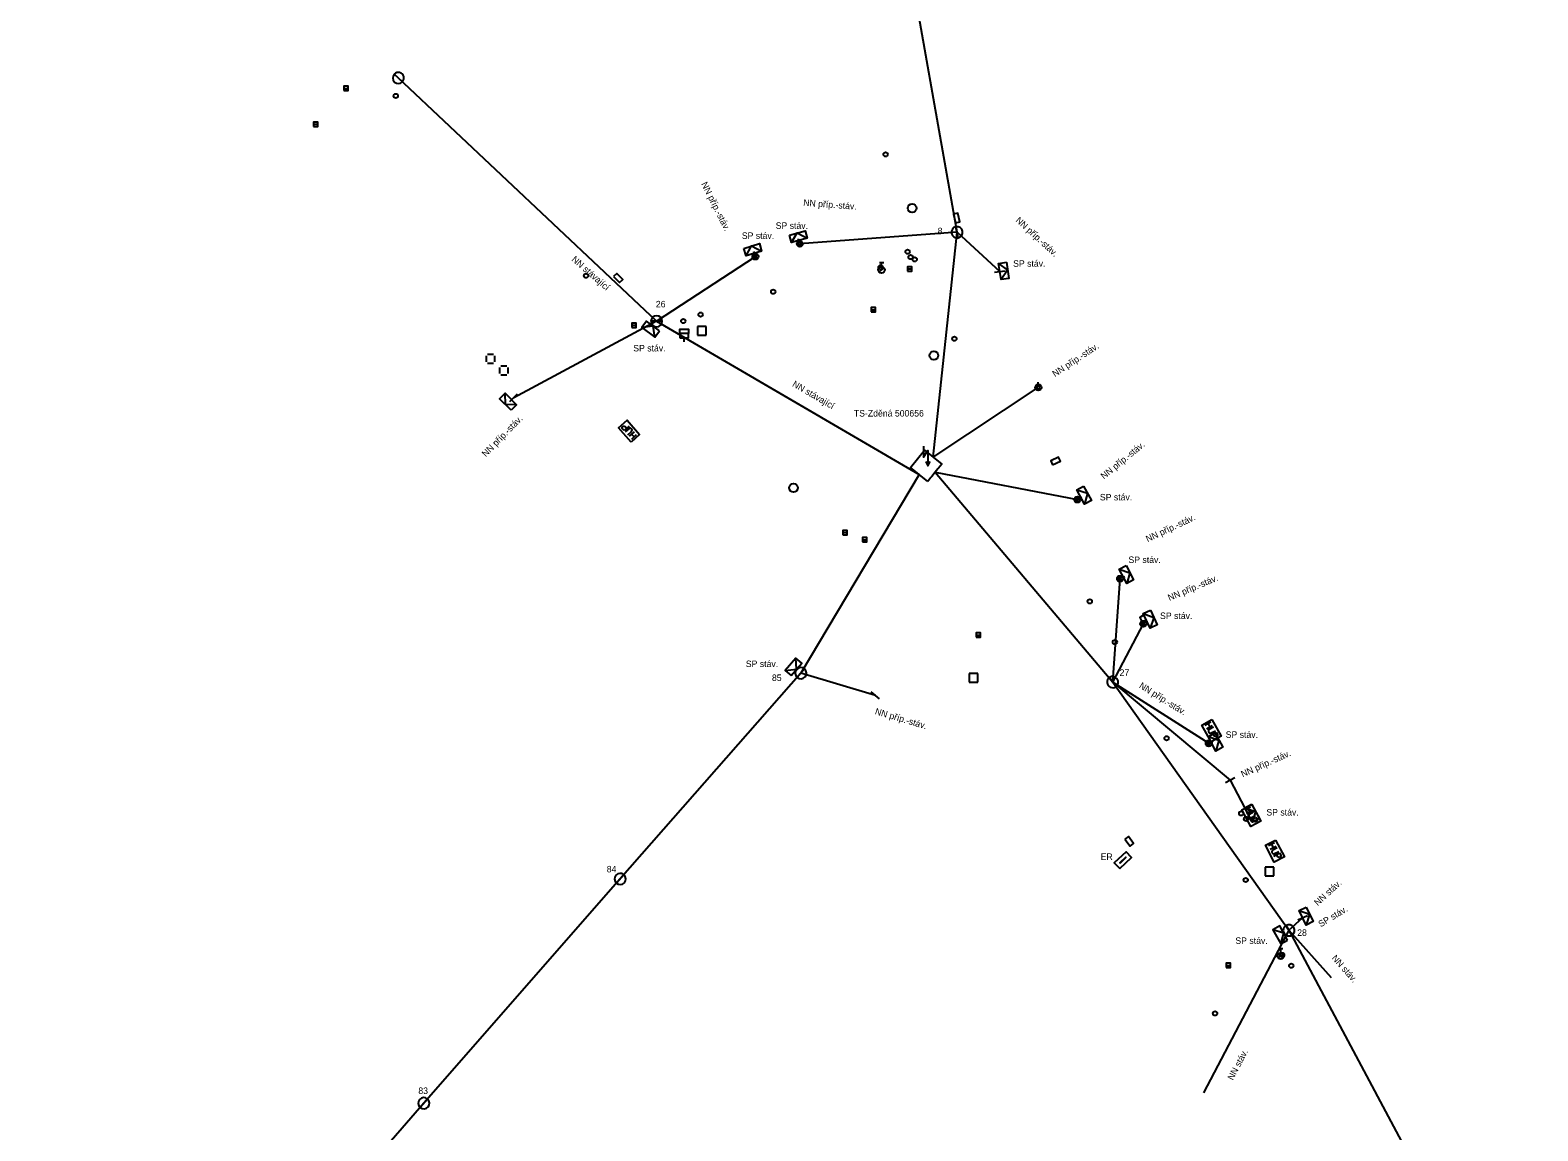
# Model space of a CAD drawing. Extents: x -577028 to -568584, y -1207664 to -1202947.
# Drawn here: x -573521.3 to -573347.2, y -1206639.6 to -1206512.4 of the extents above; entities that cross this region are included whole.
import ezdxf

# ---------------------------------------------------------------- set-up
doc = ezdxf.new("R2010")
doc.units = 0
for name, color, linetype in [('CIZÍ_NADZEM', 7, 'Continuous'), ('ELE_EON', 7, 'Continuous'), ('ELE_EON_POPIS', 7, 'Continuous')]:
    doc.layers.add(name, color=color, linetype=linetype)

msp = doc.modelspace()

# ---------------------------------------------------------------- linework, layer by layer
at = {"layer": 'CIZÍ_NADZEM'}
for p, q in [((-573485.11, -1206519.14), (-573484.61, -1206519.14)), ((-573488.61, -1206523.27), (-573488.11, -1206523.27)), ((-573423.29, -1206540.34), (-573422.7, -1206539.88)), ((-573423.25, -1206539.24), (-573422.75, -1206539.24)), ((-573423, -1206539.74), (-573423, -1206539.24)), ((-573420.02, -1206539.99), (-573419.52, -1206539.99)), ((-573424.19, -1206544.71), (-573423.69, -1206544.71)), ((-573451.86, -1206546.5), (-573451.36, -1206546.5)), ((-573443.27, -1206546.64), (-573444.27, -1206546.64)), ((-573444.27, -1206546.64), (-573444.27, -1206547.64)), ((-573443.27, -1206547.64), (-573443.27, -1206546.64)), ((-573445.81, -1206548.43), (-573445.81, -1206547.93)), ((-573444.27, -1206547.64), (-573443.27, -1206547.64)), ((-573468.65, -1206550.01), (-573468.65, -1206550.71)), ((-573467.8, -1206549.86), (-573468.5, -1206549.86)), ((-573467.65, -1206550.71), (-573467.65, -1206550.01)), ((-573468.5, -1206550.86), (-573467.8, -1206550.86)), ((-573467.13, -1206551.38), (-573467.13, -1206552.08)), ((-573466.28, -1206551.23), (-573466.98, -1206551.23)), ((-573466.98, -1206552.23), (-573466.28, -1206552.23)), ((-573466.13, -1206552.08), (-573466.13, -1206551.38)), ((-573427.48, -1206570.45), (-573426.98, -1206570.45)), ((-573425.2, -1206571.28), (-573424.7, -1206571.28)), ((-573412.09, -1206582.28), (-573411.59, -1206582.28)), ((-573411.9, -1206586.71), (-573412.9, -1206586.71)), ((-573412.9, -1206586.71), (-573412.9, -1206587.71)), ((-573411.9, -1206587.71), (-573411.9, -1206586.71)), ((-573412.9, -1206587.71), (-573411.9, -1206587.71)), ((-573377.71, -1206609.1), (-573378.71, -1206609.1)), ((-573378.71, -1206609.1), (-573378.71, -1206610.1)), ((-573377.71, -1206610.1), (-573377.71, -1206609.1)), ((-573378.71, -1206610.1), (-573377.71, -1206610.1)), ((-573377.16, -1206618.49), (-573376.66, -1206618.49)), ((-573376.91, -1206618.99), (-573376.91, -1206618.49)), ((-573377.2, -1206619.59), (-573376.61, -1206619.13)), ((-573383.22, -1206620.45), (-573382.72, -1206620.45))]:
    msp.add_line(p, q, dxfattribs=at)
for points in [[(-573485.11, -1206519.39), (-573484.61, -1206519.39), (-573484.61, -1206518.89), (-573485.11, -1206518.89)], [(-573488.61, -1206523.52), (-573488.11, -1206523.52), (-573488.11, -1206523.02), (-573488.61, -1206523.02)], [(-573414.69, -1206533.67), (-573414.45, -1206534.65), (-573413.97, -1206534.53), (-573414.21, -1206533.55)], [(-573420.02, -1206540.24), (-573419.52, -1206540.24), (-573419.52, -1206539.74), (-573420.02, -1206539.74)], [(-573453.95, -1206540.85), (-573453.25, -1206541.56), (-573452.89, -1206541.21), (-573453.59, -1206540.5)], [(-573424.19, -1206544.96), (-573423.69, -1206544.96), (-573423.69, -1206544.46), (-573424.19, -1206544.46)], [(-573451.86, -1206546.75), (-573451.36, -1206546.75), (-573451.36, -1206546.25), (-573451.86, -1206546.25)], [(-573446.31, -1206547.93), (-573445.31, -1206547.93), (-573445.31, -1206547.43), (-573446.31, -1206547.43)], [(-573403.27, -1206562.61), (-573402.35, -1206562.21), (-573402.55, -1206561.75), (-573403.47, -1206562.15)], [(-573427.48, -1206570.7), (-573426.98, -1206570.7), (-573426.98, -1206570.2), (-573427.48, -1206570.2)], [(-573425.2, -1206571.53), (-573424.7, -1206571.53), (-573424.7, -1206571.03), (-573425.2, -1206571.03)], [(-573412.09, -1206582.53), (-573411.59, -1206582.53), (-573411.59, -1206582.03), (-573412.09, -1206582.03)], [(-573394.89, -1206605.87), (-573394.28, -1206606.66), (-573393.89, -1206606.35), (-573394.5, -1206605.56)], [(-573383.22, -1206620.7), (-573382.72, -1206620.7), (-573382.72, -1206620.2), (-573383.22, -1206620.2)]]:
    msp.add_lwpolyline(points, close=True, dxfattribs=at)
for points in [[(-573446.31, -1206547.43), (-573446.31, -1206546.93), (-573445.31, -1206546.93), (-573445.31, -1206547.43)], [(-573451.92, -1206559.99), (-573453.39, -1206558.35), (-573452.4, -1206557.47), (-573450.94, -1206559.11), (-573451.92, -1206559.99)], [(-573452.74, -1206558.66), (-573452.93, -1206558.45), (-573452.97, -1206558.35), (-573452.96, -1206558.31), (-573452.93, -1206558.23), (-573452.85, -1206558.16), (-573452.77, -1206558.14), (-573452.72, -1206558.14), (-573452.63, -1206558.18), (-573452.44, -1206558.39)], [(-573452.17, -1206558.15), (-573452.74, -1206558.66)], [(-573452.3, -1206559.15), (-573451.89, -1206558.78), (-573451.83, -1206558.69), (-573451.82, -1206558.59), (-573451.86, -1206558.49), (-573451.9, -1206558.45), (-573451.99, -1206558.4), (-573452.08, -1206558.4), (-573452.19, -1206558.45), (-573452.6, -1206558.82)], [(-573451.58, -1206558.8), (-573452.16, -1206559.31)], [(-573451.59, -1206559.4), (-573451.89, -1206559.07)], [(-573451.86, -1206559.64), (-573451.29, -1206559.13)], [(-573418.15, -1206560.48), (-573418.15, -1206561.73), (-573417.65, -1206560.98), (-573417.65, -1206562.73)], [(-573417.9, -1206562.23), (-573417.65, -1206562.73), (-573417.4, -1206562.23)], [(-573392.75, -1206580), (-573393.19, -1206580.24), (-573392.92, -1206580.79), (-573392.46, -1206580.54)], [(-573384.85, -1206592.04), (-573383.78, -1206593.96), (-573384.93, -1206594.6), (-573386.01, -1206592.68), (-573384.85, -1206592.04)], [(-573384.99, -1206592.36), (-573385.66, -1206592.74)], [(-573385.44, -1206593.12), (-573384.77, -1206592.75)], [(-573385.3, -1206592.54), (-573385.09, -1206592.93)], [(-573384.66, -1206592.94), (-573385.15, -1206593.21), (-573385.23, -1206593.29), (-573385.26, -1206593.38), (-573385.24, -1206593.48), (-573385.21, -1206593.54), (-573385.14, -1206593.6), (-573385.04, -1206593.62), (-573384.93, -1206593.59), (-573384.45, -1206593.33)], [(-573385.02, -1206593.89), (-573384.34, -1206593.52)], [(-573384.34, -1206593.52), (-573384.2, -1206593.77), (-573384.19, -1206593.86), (-573384.21, -1206593.91), (-573384.25, -1206593.97), (-573384.35, -1206594.03), (-573384.43, -1206594.03), (-573384.48, -1206594.02), (-573384.55, -1206593.96), (-573384.69, -1206593.71)], [(-573380.24, -1206601.84), (-573379.21, -1206603.78), (-573380.37, -1206604.4), (-573381.41, -1206602.46), (-573380.24, -1206601.84)], [(-573380.38, -1206602.16), (-573381.06, -1206602.52)], [(-573380.85, -1206602.91), (-573380.17, -1206602.55)], [(-573380.7, -1206602.33), (-573380.49, -1206602.72)], [(-573380.07, -1206602.75), (-573380.56, -1206603), (-573380.64, -1206603.08), (-573380.67, -1206603.18), (-573380.66, -1206603.28), (-573380.63, -1206603.33), (-573380.55, -1206603.4), (-573380.46, -1206603.42), (-573380.35, -1206603.39), (-573379.86, -1206603.14)], [(-573380.44, -1206603.69), (-573379.76, -1206603.33)], [(-573379.76, -1206603.33), (-573379.63, -1206603.58), (-573379.62, -1206603.68), (-573379.63, -1206603.73), (-573379.68, -1206603.79), (-573379.78, -1206603.84), (-573379.86, -1206603.85), (-573379.9, -1206603.83), (-573379.98, -1206603.77), (-573380.11, -1206603.52)], [(-573377.5, -1206605.97), (-573376.48, -1206607.92), (-573377.65, -1206608.53), (-573378.67, -1206606.57), (-573377.5, -1206605.97)], [(-573377.64, -1206606.29), (-573378.32, -1206606.64)], [(-573378.12, -1206607.03), (-573377.43, -1206606.68)], [(-573377.96, -1206606.45), (-573377.76, -1206606.85)], [(-573377.33, -1206606.87), (-573377.82, -1206607.13), (-573377.91, -1206607.2), (-573377.94, -1206607.3), (-573377.93, -1206607.4), (-573377.9, -1206607.45), (-573377.82, -1206607.52), (-573377.73, -1206607.54), (-573377.62, -1206607.52), (-573377.13, -1206607.27)], [(-573377.71, -1206607.81), (-573377.03, -1206607.46)], [(-573377.03, -1206607.46), (-573376.9, -1206607.71), (-573376.89, -1206607.81), (-573376.91, -1206607.86), (-573376.95, -1206607.92), (-573377.05, -1206607.97), (-573377.13, -1206607.97), (-573377.18, -1206607.96), (-573377.25, -1206607.9), (-573377.38, -1206607.64)]]:
    msp.add_lwpolyline(points, dxfattribs=at)
for centre, radius in [((-573479.1, -1206520.01), 0.25), ((-573422.54, -1206526.76), 0.25), ((-573419.48, -1206532.96), 0.5), ((-573420, -1206538.01), 0.25), ((-573419.65, -1206538.63), 0.25), ((-573423, -1206540.11), 0.375), ((-573423.12, -1206539.8), 0.25), ((-573419.17, -1206538.89), 0.25), ((-573457.13, -1206540.77), 0.25), ((-573435.52, -1206542.62), 0.25), ((-573443.9, -1206545.27), 0.25), ((-573445.91, -1206546.01), 0.25), ((-573414.59, -1206548.06), 0.25), ((-573416.95, -1206549.98), 0.5), ((-573433.17, -1206565.29), 0.5), ((-573398.95, -1206578.4), 0.25), ((-573396.06, -1206583.1), 0.25), ((-573390.08, -1206594.21), 0.25), ((-573381.47, -1206602.89), 0.25), ((-573380.9, -1206603.53), 0.25), ((-573380.94, -1206610.58), 0.25), ((-573376.91, -1206619.36), 0.375), ((-573376.74, -1206619.24), 0.25), ((-573375.68, -1206620.49), 0.25), ((-573384.49, -1206626), 0.25)]:
    msp.add_circle(centre, radius, dxfattribs=at)
at = {"layer": 'ELE_EON'}
for p, q in [((-573478.34, -1206518.38), (-573479.28, -1206517.48)), ((-573432.54, -1206536.75), (-573432.61, -1206536.51)), ((-573414.15, -1206536.39), (-573414.41, -1206535.11)), ((-573437.67, -1206538.22), (-573437.74, -1206537.99)), ((-573409.96, -1206540.37), (-573408.72, -1206540.19)), ((-573448.34, -1206546.04), (-573449.64, -1206546.04)), ((-573404.9, -1206553.33), (-573404.9, -1206553.08)), ((-573465.92, -1206555.31), (-573465.04, -1206554.43)), ((-573400.09, -1206566.46), (-573399.88, -1206566.33)), ((-573395.14, -1206575.63), (-573394.92, -1206575.52)), ((-573392.49, -1206580.77), (-573392.29, -1206580.61)), ((-573431.89, -1206586.2), (-573432.75, -1206587.18)), ((-573395.94, -1206588.25), (-573396.68, -1206587.19)), ((-573423.25, -1206589.67), (-573424.19, -1206588.83)), ((-573384.91, -1206594.63), (-573384.69, -1206594.51)), ((-573383.3, -1206599.33), (-573382.2, -1206598.75)), ((-573452.76, -1206609.98), (-573453.62, -1206610.94)), ((-573374.94, -1206615.2), (-573373.8, -1206614.68)), ((-573375.63, -1206616.95), (-573376.29, -1206615.83)), ((-573475.43, -1206635.88), (-573476.29, -1206636.86))]:
    msp.add_line(p, q, dxfattribs=at)
for points in [[(-573417.05, -1206561.72), (-573414.28, -1206535.75), (-573420.64, -1206499.8), (-573424.69, -1206462.61), (-573428.74, -1206431.79), (-573432.1, -1206403.23), (-573438.62, -1206373.19), (-573445.84, -1206342.55), (-573450.84, -1206308.78)], [(-573448.99, -1206546.04), (-573478.81, -1206517.93)], [(-573433.41, -1206536.94), (-573432.75, -1206535.82), (-573431.61, -1206536.44)], [(-573414.28, -1206535.75), (-573432.44, -1206537.09), (-573432.51, -1206536.69)], [(-573414.28, -1206535.75), (-573409.34, -1206540.28)], [(-573448.99, -1206546.04), (-573437.57, -1206538.56), (-573437.75, -1206538.2)], [(-573438.65, -1206538.47), (-573438.01, -1206537.34), (-573436.85, -1206537.93)], [(-573409.48, -1206539.35), (-573408.45, -1206540.15), (-573409.2, -1206541.21)], [(-573448.99, -1206546.04), (-573465.48, -1206554.87)], [(-573449.17, -1206547.87), (-573449.39, -1206546.59), (-573450.68, -1206546.76)], [(-573448.99, -1206546.04), (-573418.66, -1206563.72)], [(-573417.05, -1206561.72), (-573404.9, -1206553.68)], [(-573465.15, -1206555.67), (-573466.45, -1206555.65), (-573466.49, -1206554.35)], [(-573417.64, -1206564.53), (-573418.66, -1206563.72), (-573419.67, -1206562.91), (-573418.06, -1206560.91), (-573417.05, -1206561.72), (-573416.04, -1206562.54), (-573416.41, -1206563), (-573416.49, -1206563.1), (-573416.8, -1206563.48), (-573417.2, -1206563.98), (-573417.3, -1206564.1), (-573417.64, -1206564.53)], [(-573418.66, -1206563.72), (-573432.32, -1206586.69), (-573453.19, -1206610.46), (-573475.86, -1206636.37), (-573498.96, -1206662.99), (-573521.33, -1206689.44)], [(-573416.8, -1206563.48), (-573396.31, -1206587.72), (-573375.96, -1206616.39), (-573362.66, -1206641.37), (-573346.27, -1206676), (-573328.79, -1206711.67), (-573315.31, -1206739.04), (-573299.98, -1206766.7), (-573284.97, -1206792.48), (-573266.37, -1206825.25), (-573246.91, -1206858.42), (-573225.83, -1206894.47), (-573202.18, -1206930.11), (-573179.91, -1206955.63), (-573153.49, -1206984.21), (-573131.71, -1207008.08)], [(-573416.8, -1206563.48), (-573400.39, -1206566.64), (-573400.01, -1206566.33)], [(-573400.46, -1206565.51), (-573399.22, -1206565.9), (-573399.56, -1206567.15)], [(-573395.55, -1206574.67), (-573394.32, -1206575.09), (-573394.69, -1206576.33)], [(-573396.31, -1206587.72), (-573395.46, -1206575.78), (-573395.12, -1206575.5)], [(-573392.78, -1206579.78), (-573391.56, -1206580.25), (-573391.98, -1206581.48)], [(-573396.31, -1206587.72), (-573392.77, -1206580.98), (-573392.38, -1206580.63)], [(-573434.13, -1206586.37), (-573432.84, -1206586.24), (-573432.9, -1206584.95)], [(-573423.72, -1206589.25), (-573432.32, -1206586.69)], [(-573396.31, -1206587.72), (-573382.75, -1206599.04), (-573380.61, -1206603.08)], [(-573396.31, -1206587.72), (-573385.22, -1206594.79), (-573384.84, -1206594.85)], [(-573385.28, -1206594.02), (-573384.05, -1206594.43), (-573384.4, -1206595.68)], [(-573381.06, -1206602.26), (-573379.82, -1206602.65), (-573380.16, -1206603.9)], [(-573375.96, -1206616.39), (-573374.37, -1206614.94)], [(-573374.79, -1206614.1), (-573373.57, -1206614.54), (-573373.95, -1206615.78)], [(-573375.96, -1206616.39), (-573385.82, -1206635.16)], [(-573376.9, -1206617.97), (-573376.56, -1206616.72), (-573377.8, -1206616.32)], [(-573375.96, -1206616.39), (-573371.07, -1206621.85)]]:
    msp.add_lwpolyline(points, dxfattribs=at)
for points in [[(-573433.65, -1206536.07), (-573431.84, -1206535.57), (-573431.61, -1206536.44), (-573433.41, -1206536.94)], [(-573438.91, -1206537.61), (-573437.11, -1206537.07), (-573436.85, -1206537.93), (-573438.65, -1206538.47)], [(-573408.59, -1206539.22), (-573408.31, -1206541.08), (-573409.2, -1206541.21), (-573409.48, -1206539.35)], [(-573448.64, -1206547.14), (-573450.15, -1206546.04), (-573450.68, -1206546.76), (-573449.17, -1206547.87)], [(-573465.79, -1206556.31), (-573467.12, -1206554.99), (-573466.49, -1206554.35), (-573465.15, -1206555.67)], [(-573399.67, -1206565.08), (-573398.77, -1206566.73), (-573399.56, -1206567.15), (-573400.46, -1206565.51)], [(-573394.75, -1206574.25), (-573393.89, -1206575.92), (-573394.69, -1206576.33), (-573395.55, -1206574.67)], [(-573391.96, -1206579.4), (-573391.17, -1206581.1), (-573391.98, -1206581.48), (-573392.78, -1206579.78)], [(-573433.45, -1206586.95), (-573432.22, -1206585.53), (-573432.9, -1206584.95), (-573434.13, -1206586.37)], [(-573384.49, -1206593.6), (-573383.6, -1206595.25), (-573384.4, -1206595.68), (-573385.28, -1206594.02)], [(-573380.27, -1206601.83), (-573379.37, -1206603.47), (-573380.16, -1206603.9), (-573381.06, -1206602.26)], [(-573395.5, -1206609.25), (-573394.14, -1206607.97), (-573394.76, -1206607.31), (-573396.12, -1206608.6)], [(-573395.46, -1206608.62), (-573394.78, -1206607.97), (-573394.8, -1206607.95), (-573395.48, -1206608.59)], [(-573373.98, -1206613.7), (-573373.15, -1206615.38), (-573373.95, -1206615.78), (-573374.79, -1206614.1)], [(-573376.11, -1206617.54), (-573377.01, -1206615.89), (-573377.8, -1206616.32), (-573376.9, -1206617.97)]]:
    msp.add_lwpolyline(points, close=True, dxfattribs=at)
for centre, radius in [((-573437.57, -1206538.56), 0.35), ((-573437.57, -1206538.56), 0.175), ((-573432.44, -1206537.09), 0.35), ((-573432.44, -1206537.09), 0.175), ((-573404.9, -1206553.68), 0.35), ((-573404.9, -1206553.68), 0.175), ((-573400.39, -1206566.64), 0.35), ((-573400.39, -1206566.64), 0.175), ((-573395.46, -1206575.78), 0.35), ((-573395.46, -1206575.78), 0.175), ((-573392.77, -1206580.98), 0.35), ((-573392.77, -1206580.98), 0.175), ((-573385.22, -1206594.79), 0.35), ((-573385.22, -1206594.79), 0.175)]:
    msp.add_circle(centre, radius, dxfattribs=at)
for centre, start, end in [((-573478.81, -1206517.93), 136.74, 316.74), ((-573478.81, -1206517.93), 316.74, 136.74), ((-573414.28, -1206535.75), 101.4251, 281.4251), ((-573414.28, -1206535.75), 281.4251, 101.4251), ((-573448.99, -1206546.04), 0, 180), ((-573448.99, -1206546.04), 180, 0), ((-573432.32, -1206586.69), 48.3665, 228.3665), ((-573432.32, -1206586.69), 228.3665, 48.3665), ((-573396.31, -1206587.72), 125.1403, 305.1403), ((-573396.31, -1206587.72), 305.1403, 125.1403), ((-573453.19, -1206610.46), 48.0128, 228.0128), ((-573453.19, -1206610.46), 228.0128, 48.0128), ((-573375.96, -1206616.39), 120.7873, 300.7873), ((-573375.96, -1206616.39), 300.7873, 120.7873), ((-573475.86, -1206636.37), 49.0122, 229.0122), ((-573475.86, -1206636.37), 229.0122, 49.0122)]:
    msp.add_arc(centre, 0.65, start, end, dxfattribs=at)

# ---------------------------------------------------------------- texts
at = {"layer": 'ELE_EON_POPIS'}
for s, rotation, p in [('NN příp.-stáv.', 296.5651, (-573443.85, -1206530.17)), ('NN příp.-stáv.', 355.6885, (-573432.07, -1206532.69)), ('NN příp.-stáv.', 317.4791, (-573407.58, -1206534.46)), ('NN stávající', 318.8597, (-573458.86, -1206538.99)), ('NN příp.-stáv.', 33.4937, (-573402.98, -1206552.5)), ('NN stávající', 329.7612, (-573433.38, -1206553.5)), ('NN příp.-stáv.', 45.5856, (-573468.71, -1206561.76)), ('NN příp.-stáv.', 39.2072, (-573397.32, -1206564.32)), ('NN příp.-stáv.', 25.1691, (-573392.27, -1206571.57)), ('NN příp.-stáv.', 22.9016, (-573389.75, -1206578.36)), ('NN příp.-stáv.', 328.134, (-573393.33, -1206588.33)), ('NN příp.-stáv.', 343.4231, (-573423.82, -1206591.41)), ('NN příp.-stáv.', 24.3257, (-573381.29, -1206598.73)), ('NN stáv.', 42.7245, (-573372.62, -1206613.61)), ('SP stáv.', 31.1538, (-573372.28, -1206616.06)), ('NN stáv.', 311.7311, (-573371.07, -1206619.64)), ('NN stáv.', 62.2389, (-573382.43, -1206633.77))]:
    msp.add_text(s, height=0.75, rotation=rotation, dxfattribs=at).set_placement(p)
for s, p in [('SP stáv.', (-573435.23, -1206535.36)), ('SP stáv.', (-573439.14, -1206536.52)), ('8', (-573416.52, -1206535.98)), ('SP stáv.', (-573407.81, -1206539.74)), ('26', (-573449.07, -1206544.43)), ('SP stáv.', (-573451.68, -1206549.52)), ('TS-Zděná 500656', (-573426.2, -1206557.04)), ('SP stáv.', (-573397.79, -1206566.73)), ('SP stáv.', (-573394.49, -1206573.96)), ('SP stáv.', (-573390.84, -1206580.43)), ('SP stáv.', (-573438.68, -1206585.98)), ('85', (-573435.66, -1206587.59)), ('27', (-573395.51, -1206587)), ('SP stáv.', (-573383.26, -1206594.16)), ('SP stáv.', (-573378.56, -1206603.13)), ('ER', (-573397.7, -1206608.26)), ('84', (-573454.74, -1206609.7)), ('28', (-573375, -1206617.03)), ('SP stáv.', (-573382.14, -1206617.96)), ('83', (-573476.5, -1206635.3))]:
    msp.add_text(s, height=0.75, dxfattribs=at).set_placement(p)

doc.saveas('drawing.dxf')
